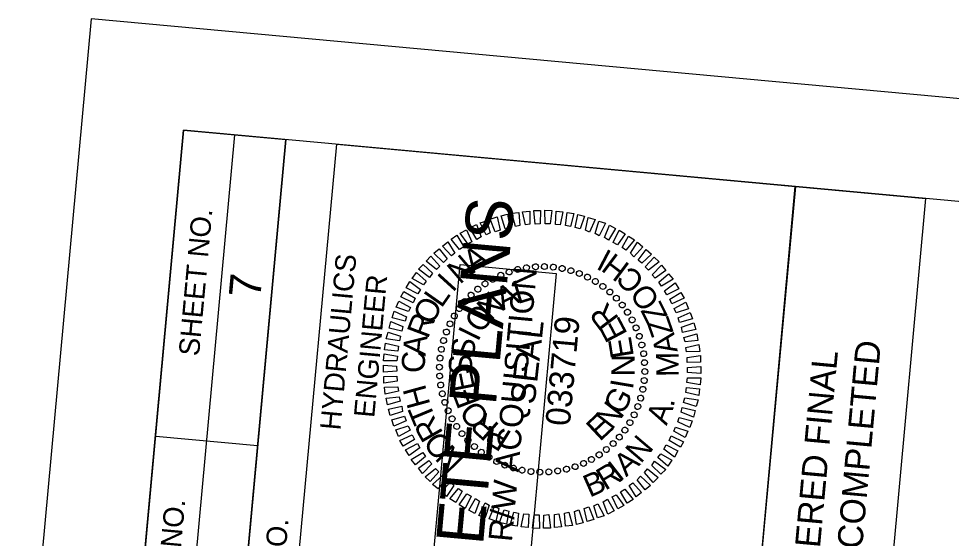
# Model space of a CAD drawing. Extents: x 2011671 to 2012922, y 444781 to 446720.
# Drawn here: x 2011808.5 to 2012036.3, y 446593.4 to 446720.2 of the extents above; entities that cross this region are included whole.
import ezdxf

# ---------------------------------------------------------------- set-up
doc = ezdxf.new("R2010")
doc.units = 0
for name, color, linetype in [('Sheet Data Field CELL', 7, 'Continuous'), ('Sheet Plan And Profile CELL', 7, 'Continuous'), ('Sheet Plot Border Outside CELL', 7, 'Continuous'), ('Sheet Professional Seal CELL', 7, 'Continuous'), ('Sheet Profile Grid Minor CELL', 7, 'Continuous'), ('Sheet Sticker Exception Certification CELL', 7, 'Continuous'), ('Sheet Sticker Incomplete CELL', 7, 'Continuous')]:
    doc.layers.add(name, color=color, linetype=linetype)

msp = doc.modelspace()

# ---------------------------------------------------------------- linework, layer by layer
at = {"layer": 'Sheet Plan And Profile CELL'}
for p, q in [((2011842.98, 446492.7), (2011861.29, 446691.91)), ((2011855.42, 446491.55), (2011873.74, 446690.76)), ((2011841.98, 446618.37), (2011866.87, 446616.08))]:
    msp.add_line(p, q, dxfattribs=at)
for points in [[(2011848.79, 446693.05), (2011711.46, 445199.36), (2012757.04, 445103.22), (2012894.38, 446596.92)], [(2011830.48, 446493.85), (2011848.79, 446693.05), (2011873.74, 446690.76), (2011855.42, 446491.55)], [(2011877.03, 446590.04), (2011886.19, 446689.62), (2011998.21, 446679.32), (2011989.06, 446579.74)]]:
    msp.add_lwpolyline(points, close=True, dxfattribs=at)
at = {"layer": 'Sheet Plot Border Outside CELL'}
msp.add_lwpolyline([(2012765.92, 444926.66), (2012921.57, 446619.52), (2011826.19, 446720.24), (2011670.54, 445027.38)], close=True, dxfattribs=at)
at = {"layer": 'Sheet Professional Seal CELL'}
for p, q in [((2011928.3, 446658.47), (2011928.3, 446658.47)), ((2011930.37, 446659.09), (2011930.37, 446659.09)), ((2011932.51, 446659.49), (2011932.51, 446659.49)), ((2011934.74, 446659.69), (2011934.74, 446659.69)), ((2011936.91, 446659.79), (2011936.91, 446659.79)), ((2011939.1, 446659.64), (2011939.1, 446659.64)), ((2011941.28, 446659.29), (2011941.28, 446659.29)), ((2011943.39, 446658.74), (2011943.39, 446658.74)), ((2011945.44, 446658.1), (2011945.44, 446658.1)), ((2011922.41, 446655.6), (2011922.41, 446655.6)), ((2011924.27, 446656.68), (2011924.27, 446656.68)), ((2011926.27, 446657.65), (2011926.27, 446657.65)), ((2011947.47, 446657.21), (2011947.47, 446657.21)), ((2011949.38, 446656.13), (2011949.38, 446656.13)), ((2011920.63, 446654.26), (2011920.63, 446654.26)), ((2011951.23, 446654.96), (2011951.23, 446654.96)), ((2011952.9, 446653.55), (2011952.9, 446653.55)), ((2011917.49, 446651.23), (2011917.49, 446651.23)), ((2011919, 446652.85), (2011919, 446652.85)), ((2011954.52, 446652.04), (2011954.52, 446652.04)), ((2011916.08, 446649.55), (2011916.08, 446649.55)), ((2011955.93, 446650.41), (2011955.93, 446650.41)), ((2011957.27, 446648.63), (2011957.27, 446648.63)), ((2011914.91, 446647.7), (2011914.91, 446647.7)), ((2011958.36, 446646.77), (2011958.36, 446646.77)), ((2011913.83, 446645.79), (2011913.83, 446645.79)), ((2011959.33, 446644.77), (2011959.33, 446644.77)), ((2011912.3, 446641.72), (2011912.3, 446641.72)), ((2011912.94, 446643.77), (2011912.94, 446643.77)), ((2011960.15, 446642.74), (2011960.15, 446642.74)), ((2011911.76, 446639.61), (2011911.76, 446639.61)), ((2011960.76, 446640.68), (2011960.76, 446640.68)), ((2011911.4, 446637.43), (2011911.4, 446637.43)), ((2011961.16, 446638.53), (2011961.16, 446638.53)), ((2011911.25, 446635.24), (2011911.25, 446635.24)), ((2011961.36, 446636.3), (2011961.36, 446636.3)), ((2011911.35, 446633.07), (2011911.35, 446633.07)), ((2011936.36, 446634.68), (2011936.36, 446634.68)), ((2011961.46, 446634.13), (2011961.46, 446634.13)), ((2011911.55, 446630.84), (2011911.55, 446630.84)), ((2011961.31, 446631.94), (2011961.31, 446631.94)), ((2011911.96, 446628.69), (2011911.96, 446628.69)), ((2011960.96, 446629.76), (2011960.96, 446629.76)), ((2011912.57, 446626.63), (2011912.57, 446626.63)), ((2011960.41, 446627.65), (2011960.41, 446627.65)), ((2011913.39, 446624.6), (2011913.39, 446624.6)), ((2011958.89, 446623.58), (2011958.89, 446623.58)), ((2011959.77, 446625.6), (2011959.77, 446625.6)), ((2011914.36, 446622.6), (2011914.36, 446622.6)), ((2011957.81, 446621.67), (2011957.81, 446621.67)), ((2011915.44, 446620.74), (2011915.44, 446620.74)), ((2011916.79, 446618.96), (2011916.79, 446618.96)), ((2011956.63, 446619.82), (2011956.63, 446619.82)), ((2011918.19, 446617.32), (2011918.19, 446617.32)), ((2011955.22, 446618.14), (2011955.22, 446618.14)), ((2011919.81, 446615.82), (2011919.81, 446615.82)), ((2011921.49, 446614.41), (2011921.49, 446614.41)), ((2011952.08, 446615.11), (2011952.08, 446615.11)), ((2011953.72, 446616.52), (2011953.72, 446616.52)), ((2011923.34, 446613.24), (2011923.34, 446613.24)), ((2011925.25, 446612.16), (2011925.25, 446612.16)), ((2011948.44, 446612.69), (2011948.44, 446612.69)), ((2011950.3, 446613.77), (2011950.3, 446613.77)), ((2011927.28, 446611.27), (2011927.28, 446611.27)), ((2011929.33, 446610.63), (2011929.33, 446610.63)), ((2011931.43, 446610.08), (2011931.43, 446610.08)), ((2011940.2, 446609.88), (2011940.2, 446609.88)), ((2011942.35, 446610.28), (2011942.35, 446610.28)), ((2011944.41, 446610.9), (2011944.41, 446610.9)), ((2011946.45, 446611.71), (2011946.45, 446611.71)), ((2011933.61, 446609.73), (2011933.61, 446609.73)), ((2011935.81, 446609.58), (2011935.81, 446609.58)), ((2011937.98, 446609.68), (2011937.98, 446609.68))]:
    msp.add_line(p, q, dxfattribs=at)
for points in [[(2011924.93, 446668.27), (2011923.71, 446671.35), (2011925.36, 446671.85), (2011926.08, 446668.67)], [(2011927.36, 446668.95), (2011926.34, 446672.11), (2011927.94, 446672.51), (2011928.45, 446669.35)], [(2011929.82, 446669.53), (2011928.97, 446672.82), (2011930.64, 446672.97), (2011930.9, 446669.78)], [(2011932.27, 446669.91), (2011931.61, 446673.13), (2011933.33, 446673.27), (2011933.34, 446670.11)], [(2011934.7, 446670.14), (2011934.3, 446673.44), (2011936, 446673.43), (2011935.91, 446670.22)], [(2011937.11, 446670.21), (2011937.01, 446673.49), (2011938.72, 446673.43), (2011938.32, 446670.2)], [(2011939.61, 446670.04), (2011939.76, 446673.29), (2011941.45, 446673.13), (2011940.8, 446669.93)], [(2011942.09, 446669.76), (2011942.49, 446672.98), (2011944.12, 446672.73), (2011943.28, 446669.55)], [(2011944.46, 446669.29), (2011945.05, 446672.45), (2011946.73, 446672.09), (2011945.63, 446668.93)], [(2011946.96, 446668.66), (2011947.64, 446671.71), (2011949.31, 446671.2), (2011947.97, 446668.16)], [(2011920.39, 446666.38), (2011918.74, 446669.19), (2011920.32, 446670), (2011921.45, 446666.98)], [(2011922.7, 446667.47), (2011921.22, 446670.42), (2011922.82, 446670.93), (2011923.7, 446667.98)], [(2011949.29, 446667.79), (2011950.22, 446670.82), (2011951.84, 446670.32), (2011950.3, 446667.29)], [(2011951.61, 446666.82), (2011952.79, 446669.83), (2011954.28, 446669.04), (2011952.61, 446666.18)], [(2011916.15, 446663.96), (2011914.12, 446666.45), (2011915.56, 446667.38), (2011917.21, 446664.56)], [(2011918.23, 446665.27), (2011916.37, 446667.9), (2011917.9, 446668.72), (2011919.23, 446665.78)], [(2011953.71, 446665.63), (2011955.14, 446668.61), (2011956.62, 446667.72), (2011954.76, 446665.03)], [(2011955.91, 446664.42), (2011957.42, 446667.14), (2011958.89, 446666.25), (2011956.8, 446663.73)], [(2011914.2, 446662.38), (2011912.06, 446664.74), (2011913.36, 446665.82), (2011915.07, 446663.05)], [(2011957.94, 446663.03), (2011959.69, 446665.68), (2011961, 446664.55), (2011958.77, 446662.15)], [(2011910.58, 446659), (2011908.01, 446661.09), (2011909.22, 446662.29), (2011911.36, 446659.88)], [(2011912.29, 446660.75), (2011909.89, 446663.03), (2011911.2, 446664.11), (2011913.13, 446661.62)], [(2011959.8, 446661.35), (2011961.74, 446663.88), (2011963.09, 446662.8), (2011960.68, 446660.62)], [(2011908.89, 446657.09), (2011906.17, 446659.1), (2011907.33, 446660.3), (2011909.59, 446658.13)], [(2011961.55, 446659.68), (2011963.73, 446662.09), (2011964.93, 446660.88), (2011962.38, 446658.9)], [(2011963.28, 446657.77), (2011965.56, 446660.12), (2011966.59, 446658.77), (2011964.01, 446656.9)], [(2011907.37, 446655.27), (2011904.66, 446656.88), (2011905.64, 446658.3), (2011908.06, 446656.17)], [(2011964.88, 446655.96), (2011967.27, 446657.95), (2011968.35, 446656.65), (2011965.49, 446654.95)], [(2011906.02, 446653.09), (2011903.19, 446654.6), (2011904.03, 446656.08), (2011906.66, 446654.13)], [(2011966.24, 446653.83), (2011968.82, 446655.75), (2011969.74, 446654.31), (2011966.8, 446652.82)], [(2011904.86, 446650.94), (2011901.83, 446652.37), (2011902.56, 446653.71), (2011905.32, 446652.05)], [(2011967.56, 446651.8), (2011970.26, 446653.41), (2011971.09, 446652.03), (2011968.05, 446650.65)], [(2011903.76, 446648.78), (2011900.74, 446649.81), (2011901.38, 446651.31), (2011904.21, 446649.79)], [(2011968.6, 446649.49), (2011971.46, 446651.09), (2011972.11, 446649.47), (2011969.11, 446648.49)], [(2011902.89, 446646.45), (2011899.7, 446647.24), (2011900.26, 446648.9), (2011903.24, 446647.47)], [(2011969.6, 446647.24), (2011972.53, 446648.58), (2011973.09, 446646.97), (2011969.94, 446646.11)], [(2011902.11, 446643.96), (2011898.97, 446644.7), (2011899.37, 446646.32), (2011902.37, 446645.14)], [(2011970.44, 446644.96), (2011973.45, 446645.99), (2011973.91, 446644.44), (2011970.63, 446643.68)], [(2011901.49, 446641.61), (2011898.28, 446642.1), (2011898.73, 446643.72), (2011901.8, 446642.78)], [(2011971.01, 446642.44), (2011974.11, 446643.31), (2011974.41, 446641.73), (2011971.27, 446641.37)], [(2011901.12, 446639.13), (2011897.88, 446639.43), (2011898.08, 446641.07), (2011901.28, 446640.32)], [(2011971.44, 446639.99), (2011974.67, 446640.75), (2011974.87, 446639.03), (2011971.59, 446638.93)], [(2011900.85, 446636.74), (2011897.59, 446636.79), (2011897.79, 446638.43), (2011901.01, 446637.93)], [(2011971.77, 446637.55), (2011975.03, 446638.06), (2011975.03, 446636.4), (2011971.81, 446636.35)], [(2011900.87, 446634.23), (2011897.63, 446633.98), (2011897.59, 446635.69), (2011900.83, 446635.44)], [(2011971.85, 446635.14), (2011975.09, 446635.39), (2011975.13, 446633.68), (2011971.89, 446633.93)], [(2011900.95, 446631.81), (2011897.69, 446631.31), (2011897.69, 446632.97), (2011900.91, 446633.02)], [(2011971.87, 446632.62), (2011975.13, 446632.58), (2011974.93, 446630.94), (2011971.71, 446631.43)], [(2011901.27, 446629.37), (2011898.04, 446628.62), (2011897.85, 446630.34), (2011901.12, 446630.44)], [(2011971.6, 446630.24), (2011974.84, 446629.94), (2011974.63, 446628.3), (2011971.44, 446629.05)], [(2011901.7, 446626.92), (2011898.61, 446626.05), (2011898.3, 446627.64), (2011901.45, 446628)], [(2011971.22, 446627.76), (2011974.44, 446627.27), (2011973.99, 446625.65), (2011970.91, 446626.59)], [(2011902.27, 446624.41), (2011899.27, 446623.38), (2011898.81, 446624.93), (2011902.09, 446625.68)], [(2011970.6, 446625.41), (2011973.75, 446624.67), (2011973.35, 446623.05), (2011970.34, 446624.23)], [(2011903.12, 446622.13), (2011900.18, 446620.79), (2011899.63, 446622.4), (2011902.77, 446623.26)], [(2011969.82, 446622.92), (2011973.01, 446622.13), (2011972.46, 446620.47), (2011969.48, 446621.9)], [(2011904.12, 446619.87), (2011901.26, 446618.28), (2011900.6, 446619.9), (2011903.61, 446620.88)], [(2011968.95, 446620.59), (2011971.97, 446619.56), (2011971.33, 446618.06), (2011968.51, 446619.58)], [(2011905.16, 446617.57), (2011902.45, 446615.96), (2011901.62, 446617.34), (2011904.66, 446618.72)], [(2011967.85, 446618.43), (2011970.88, 446617), (2011970.16, 446615.66), (2011967.4, 446617.32)], [(2011906.48, 446615.54), (2011903.89, 446613.62), (2011902.97, 446615.06), (2011905.92, 446616.55)], [(2011907.84, 446613.41), (2011905.45, 446611.42), (2011904.36, 446612.72), (2011907.23, 446614.42)], [(2011966.7, 446616.28), (2011969.52, 446614.76), (2011968.68, 446613.28), (2011966.05, 446615.23)], [(2011909.43, 446611.6), (2011907.16, 446609.25), (2011906.13, 446610.6), (2011908.71, 446612.47)], [(2011963.82, 446612.28), (2011966.55, 446610.27), (2011965.38, 446609.07), (2011963.12, 446611.24)], [(2011965.34, 446614.09), (2011968.06, 446612.49), (2011967.07, 446611.07), (2011964.66, 446613.2)], [(2011911.16, 446609.69), (2011908.98, 446607.28), (2011907.79, 446608.49), (2011910.33, 446610.47)], [(2011962.14, 446610.37), (2011964.71, 446608.28), (2011963.49, 446607.08), (2011961.36, 446609.49)], [(2011912.92, 446608.02), (2011910.98, 446605.49), (2011909.62, 446606.56), (2011912.03, 446608.75)], [(2011960.42, 446608.62), (2011962.82, 446606.34), (2011961.52, 446605.26), (2011959.59, 446607.74)], [(2011914.77, 446606.34), (2011913.02, 446603.69), (2011911.72, 446604.81), (2011913.95, 446607.22)], [(2011916.8, 446604.95), (2011915.3, 446602.23), (2011913.82, 446603.12), (2011915.91, 446605.63)], [(2011956.56, 446605.41), (2011958.59, 446602.92), (2011957.15, 446601.99), (2011955.5, 446604.81)], [(2011958.51, 446606.99), (2011960.66, 446604.63), (2011959.35, 446603.55), (2011957.65, 446606.32)], [(2011919, 446603.74), (2011917.57, 446600.76), (2011916.1, 446601.65), (2011917.95, 446604.34)], [(2011921.1, 446602.55), (2011919.92, 446599.54), (2011918.44, 446600.33), (2011920.11, 446603.19)], [(2011952.32, 446602.99), (2011953.97, 446600.18), (2011952.39, 446599.37), (2011951.26, 446602.38)], [(2011954.48, 446604.1), (2011956.35, 446601.46), (2011954.82, 446600.65), (2011953.48, 446603.59)], [(2011923.42, 446601.58), (2011922.49, 446598.55), (2011920.88, 446599.05), (2011922.41, 446602.07)], [(2011925.75, 446600.71), (2011925.07, 446597.66), (2011923.41, 446598.17), (2011924.74, 446601.21)], [(2011947.78, 446601.1), (2011949, 446598.02), (2011947.35, 446597.52), (2011946.64, 446600.7)], [(2011950.01, 446601.9), (2011951.5, 446598.95), (2011949.9, 446598.44), (2011949.01, 446601.39)], [(2011928.26, 446600.08), (2011927.66, 446596.92), (2011925.99, 446597.28), (2011927.08, 446600.44)], [(2011930.62, 446599.61), (2011930.23, 446596.39), (2011928.59, 446596.64), (2011929.44, 446599.82)], [(2011933.11, 446599.33), (2011932.96, 446596.08), (2011931.27, 446596.24), (2011931.91, 446599.44)], [(2011935.6, 446599.15), (2011935.7, 446595.88), (2011934, 446595.94), (2011934.4, 446599.16)], [(2011938.02, 446599.23), (2011938.42, 446595.93), (2011936.71, 446595.94), (2011936.81, 446599.14)], [(2011940.45, 446599.46), (2011941.11, 446596.24), (2011939.39, 446596.09), (2011939.38, 446599.26)], [(2011942.89, 446599.84), (2011943.75, 446596.55), (2011942.08, 446596.4), (2011941.82, 446599.59)], [(2011945.36, 446600.42), (2011946.37, 446597.26), (2011944.78, 446596.85), (2011944.27, 446600.01)]]:
    msp.add_lwpolyline(points, close=True, dxfattribs=at)
for centre, major_axis in [((2011932.54, 446659.47), (-0.109, 0.712)), ((2011934.72, 446659.71), (-0.047, 0.718)), ((2011936.91, 446659.76), (0.016, 0.72)), ((2011939.09, 446659.62), (0.078, 0.716)), ((2011941.25, 446659.28), (0.141, 0.706)), ((2011926.26, 446657.64), (-0.29, 0.659)), ((2011928.3, 446658.43), (-0.231, 0.682)), ((2011930.4, 446659.05), (-0.171, 0.699)), ((2011943.38, 446658.76), (0.202, 0.691)), ((2011945.45, 446658.06), (0.261, 0.671)), ((2011947.45, 446657.18), (0.318, 0.646)), ((2011922.43, 446655.54), (-0.4, 0.599)), ((2011924.3, 446656.67), (-0.346, 0.631)), ((2011949.37, 446656.12), (0.374, 0.616)), ((2011951.19, 446654.91), (0.426, 0.581)), ((2011919.02, 446652.8), (-0.498, 0.52)), ((2011920.66, 446654.24), (-0.451, 0.562)), ((2011952.9, 446653.54), (0.475, 0.541)), ((2011917.5, 446651.22), (-0.541, 0.475)), ((2011954.48, 446652.03), (0.52, 0.498)), ((2011955.92, 446650.38), (0.562, 0.451)), ((2011916.13, 446649.52), (-0.581, 0.426)), ((2011957.21, 446648.62), (0.599, 0.4)), ((2011913.86, 446645.78), (-0.646, 0.318)), ((2011914.92, 446647.7), (-0.616, 0.374)), ((2011958.35, 446646.75), (0.631, 0.346)), ((2011912.98, 446643.78), (-0.671, 0.261)), ((2011959.31, 446644.78), (0.659, 0.29)), ((2011912.28, 446641.7), (-0.691, 0.202)), ((2011960.11, 446642.74), (0.682, 0.231)), ((2011911.76, 446639.58), (-0.706, 0.141)), ((2011960.72, 446640.64), (0.699, 0.171)), ((2011911.43, 446637.42), (-0.716, 0.078)), ((2011961.15, 446638.5), (0.712, 0.109)), ((2011911.28, 446635.23), (-0.72, 0.016)), ((2011961.38, 446636.32), (0.718, 0.047)), ((2011911.33, 446633.05), (-0.718, -0.047)), ((2011961.29, 446631.95), (0.716, -0.078)), ((2011961.43, 446634.14), (0.72, -0.016)), ((2011911.57, 446630.87), (-0.712, -0.109)), ((2011960.96, 446629.79), (0.706, -0.141)), ((2011912, 446628.72), (-0.699, -0.171)), ((2011960.44, 446627.66), (0.691, -0.202)), ((2011912.61, 446626.62), (-0.682, -0.231)), ((2011959.73, 446625.59), (0.671, -0.261)), ((2011913.4, 446624.58), (-0.659, -0.29)), ((2011958.85, 446623.59), (0.646, -0.318)), ((2011914.37, 446622.62), (-0.631, -0.346)), ((2011915.5, 446620.75), (-0.599, -0.4)), ((2011957.8, 446621.67), (0.616, -0.374)), ((2011916.8, 446618.99), (-0.562, -0.451)), ((2011955.21, 446618.15), (0.541, -0.475)), ((2011956.58, 446619.85), (0.581, -0.426)), ((2011918.24, 446617.34), (-0.52, -0.498)), ((2011953.7, 446616.57), (0.498, -0.52)), ((2011919.82, 446615.83), (-0.475, -0.541)), ((2011921.53, 446614.46), (-0.426, -0.581)), ((2011950.29, 446613.83), (0.4, -0.599)), ((2011952.05, 446615.12), (0.451, -0.562)), ((2011923.35, 446613.24), (-0.374, -0.616)), ((2011925.26, 446612.19), (-0.318, -0.646)), ((2011927.27, 446611.31), (-0.261, -0.671)), ((2011946.46, 446611.73), (0.29, -0.659)), ((2011948.42, 446612.7), (0.346, -0.631)), ((2011929.34, 446610.61), (-0.202, -0.691)), ((2011931.46, 446610.09), (-0.141, -0.706)), ((2011933.63, 446609.75), (-0.078, -0.716)), ((2011935.81, 446609.61), (-0.016, -0.72)), ((2011938, 446609.66), (0.047, -0.718)), ((2011940.17, 446609.9), (0.109, -0.712)), ((2011942.32, 446610.32), (0.171, -0.699)), ((2011944.42, 446610.93), (0.231, -0.682))]:
    msp.add_ellipse(centre, major_axis=major_axis, ratio=0.999708, dxfattribs=at)
at = {"layer": 'Sheet Sticker Exception Certification CELL'}
for p, q in [((2011979.88, 446480.11), (2011998.2, 446679.32)), ((2011998.21, 446679.32), (2012030.06, 446676.39)), ((2012030.04, 446676.39), (2012011.73, 446477.18))]:
    msp.add_line(p, q, dxfattribs=at)
at = {"layer": 'Sheet Sticker Incomplete CELL'}
msp.add_lwpolyline([(2011926.32, 446511.7), (2011902.91, 446513.85), (2011916.37, 446660.23), (2011939.77, 446658.08)], close=True, dxfattribs=at)

# ---------------------------------------------------------------- texts
at = {"layer": 'Sheet Data Field CELL'}
msp.add_text('7', height=7.75, rotation=84.7467, dxfattribs=at).set_placement((2011867.51, 446651.9))
at = {"layer": 'Sheet Plan And Profile CELL'}
for s, height, p in [('SHEET NO.', 5, (2011852.55, 446637.78)), ('HYDRAULICS', 5, (2011887.09, 446619.69)), ('ENGINEER', 5, (2011895.35, 446622.75)), ('PROJECT REFERENCE NO.', 5.0001, (2011841.17, 446515.16)), ('R/W SHEET NO.', 5.0001, (2011869.8, 446547.47))]:
    msp.add_text(s, height=height, rotation=84.7467, dxfattribs=at).set_placement(p)
at = {"layer": 'Sheet Professional Seal CELL'}
for s, height, rotation, p in [('N', 5.64, 40.5656, (2011916.26, 446655.26)), ('A', 5.64, 33.3638, (2011919.46, 446657.93)), ('I', 5.64, 47.7668, (2011914.52, 446653.26)), ('L', 5.64, 17.1475, (2011930.34, 446650.55)), ('L', 5.64, 54.9675, (2011911.76, 446649.45)), ('N', 5.64, 45.2233, (2011923.87, 446646.33)), ('A', 5.64, 26.5069, (2011926.72, 446648.93)), ('O', 5.64, 62.1678, (2011909.51, 446645.24)), ('R', 5.64, 127.2281, (2011955.32, 446647.1)), ('O', 5.64, 54.5801, (2011921.57, 446643.17)), ('R', 5.64, 69.3678, (2011908.46, 446641.97)), ('E', 5.64, 117.8707, (2011957.34, 446643.35)), ('I', 5.64, 63.9363, (2011920.69, 446641.25)), ('SEAL', 5.998, 83.7467, (2011934.55, 446625.96)), ('A', 5.64, 83.767, (2011907.87, 446637.81)), ('S', 5.64, 82.6471, (2011919.6, 446637.03)), ('E', 5.64, 99.1584, (2011958.8, 446637.89)), ('C', 5.64, 90.9665, (2011907.81, 446633.84)), ('S', 5.64, 92.0023, (2011919.32, 446633.44)), ('N', 5.64, 89.803, (2011958.94, 446632.91)), ('E', 5.64, 101.3577, (2011920.05, 446629.91)), ('H', 5.64, 105.3661, (2011909.11, 446626.09)), ('I', 5.64, 80.4479, (2011958.48, 446629.59)), ('F', 5.64, 110.7137, (2011921.25, 446626.58)), ('G', 5.64, 61.7369, (2011955.99, 446623.24)), ('O', 5.64, 129.4279, (2011923.89, 446623.03)), ('N', 5.64, 52.3806, (2011953.4, 446619.66)), ('T', 5.64, 112.5664, (2011910.45, 446622.71)), ('R', 5.64, 119.7672, (2011912.33, 446619.12)), ('R', 5.64, 138.7863, (2011926.17, 446621.06)), ('E', 5.64, 43.0235, (2011950.44, 446616.92)), ('P', 5.64, 148.1455, (2011929.21, 446619.17)), ('O', 5.64, 126.9684, (2011915.1, 446615.4)), ('N', 5.64, 134.1702, (2011917.78, 446612.84))]:
    msp.add_text(s, height=height, rotation=rotation, dxfattribs=at).set_placement(p)
at = {"layer": 'Sheet Profile Grid Minor CELL'}
for s, height, rotation, p in [('I', 5.5, 152.3393, (2011953.68, 446663.27)), ('H', 5.5, 143.0945, (2011958.05, 446660.12)), ('C', 5.5, 134.2218, (2011961.71, 446656.47)), ('O', 5.5, 123.5173, (2011965.32, 446651.38)), ('Z', 5.5, 116.3905, (2011967.17, 446647.66)), ('033719', 5.998, 84.7467, (2011943.11, 446620.69)), ('Z', 5.5, 109.2637, (2011968.54, 446643.73)), ('A', 5.5, 101.0779, (2011969.5, 446639.06)), ('M', 5.5, 90.402, (2011969.74, 446632.84)), ('.', 5.5, 77.2217, (2011968.44, 446625.28)), ('A', 5.5, 69.0359, (2011966.77, 446620.81)), ('N', 5.5, 49.6591, (2011960.44, 446611.51)), ('I', 5.5, 37.9528, (2011955.24, 446607.1)), ('A', 5.5, 41.4733, (2011956.9, 446608.31)), ('B', 5.5, 23.8996, (2011947.98, 446603.34)), ('R', 5.5, 31.0264, (2011951.78, 446605.02))]:
    msp.add_text(s, height=height, rotation=rotation, dxfattribs=at).set_placement(p)
at = {"layer": 'Sheet Sticker Exception Certification CELL'}
for s, p in [('UNLESS ALL SIGNATURES COMPLETED', (2012004.66, 446483.75)), ('DOCUMENT NOT CONSIDERED FINAL', (2011994.97, 446490.4))]:
    msp.add_text(s, height=6.124, rotation=84.7467, dxfattribs=at).set_placement(p)
at = {"layer": 'Sheet Sticker Incomplete CELL'}
for s, height, p in [('INCOMPLETE PLANS', 11.52, (2011915.48, 446521.68)), ('DO NOT USE FOR R/W ACQUISITION', 5.76, (2011922.7, 446524.28))]:
    msp.add_text(s, height=height, rotation=84.7467, dxfattribs=at).set_placement(p)

doc.saveas('drawing.dxf')
